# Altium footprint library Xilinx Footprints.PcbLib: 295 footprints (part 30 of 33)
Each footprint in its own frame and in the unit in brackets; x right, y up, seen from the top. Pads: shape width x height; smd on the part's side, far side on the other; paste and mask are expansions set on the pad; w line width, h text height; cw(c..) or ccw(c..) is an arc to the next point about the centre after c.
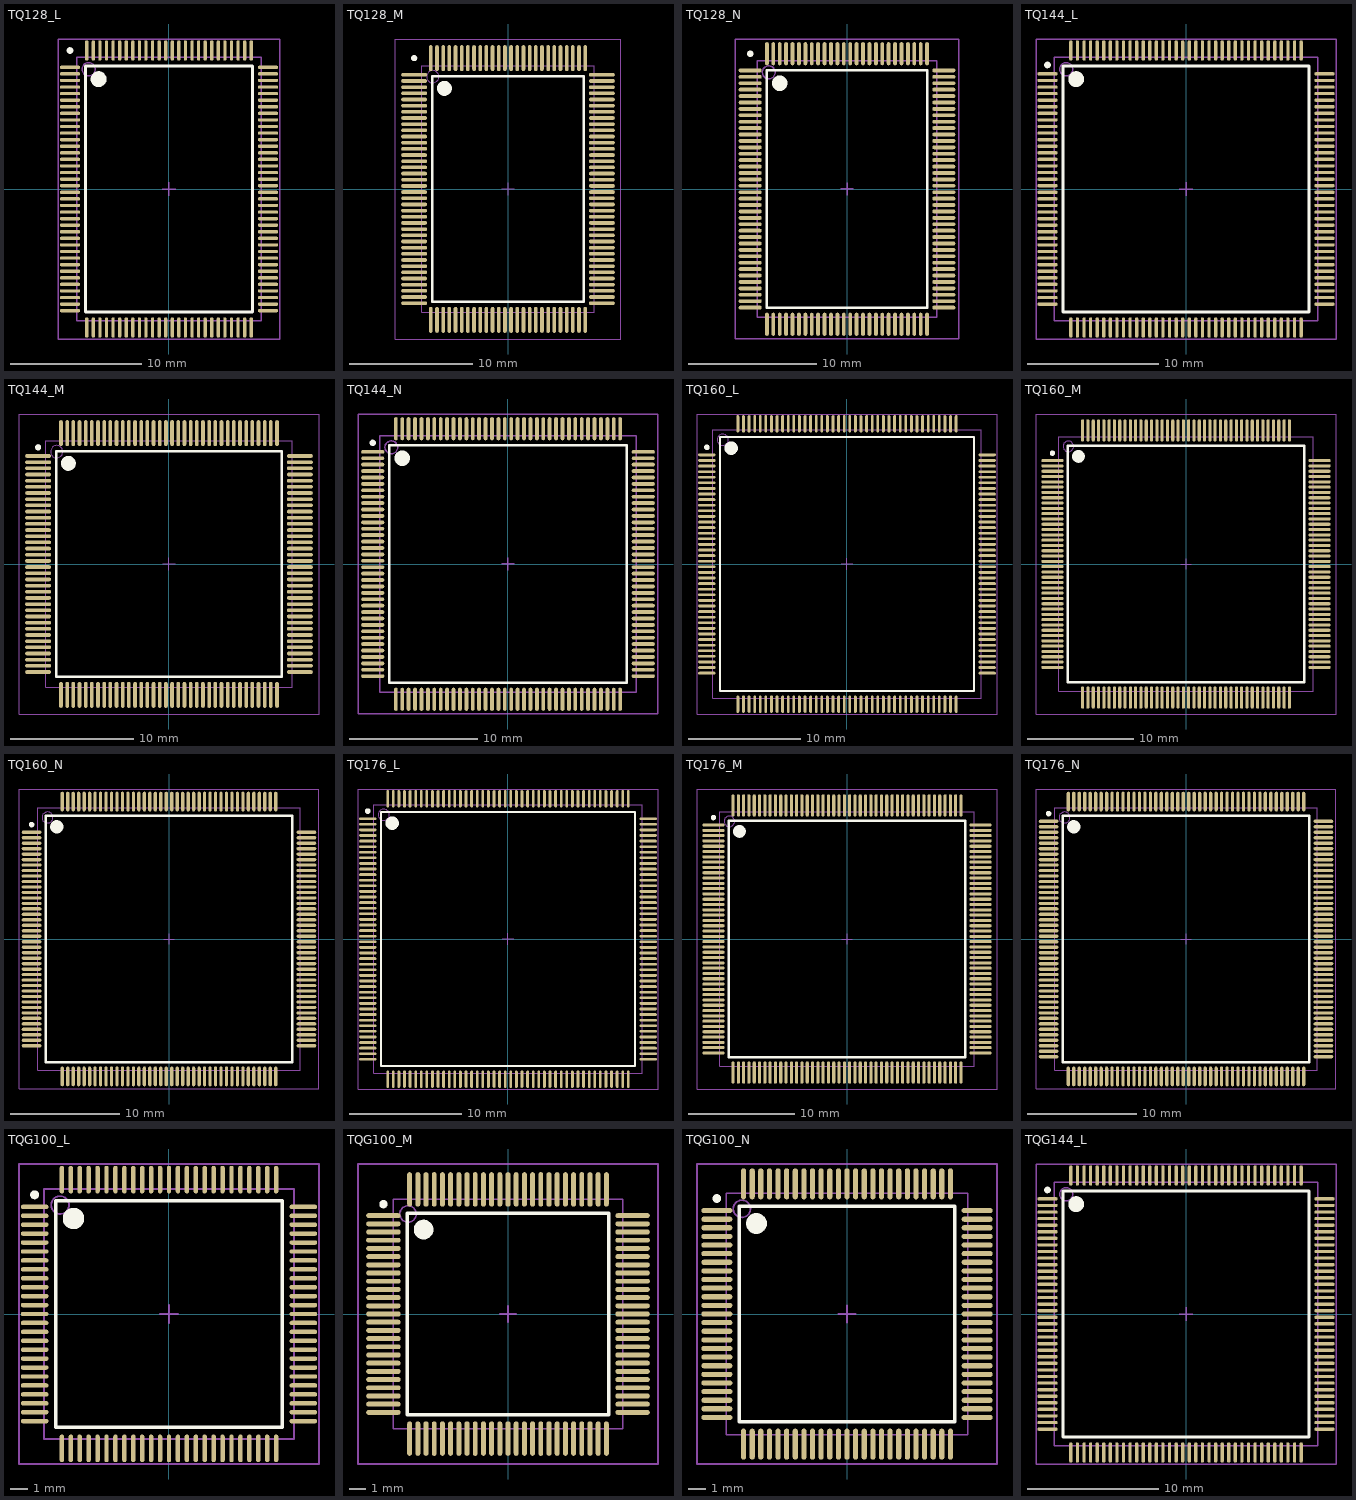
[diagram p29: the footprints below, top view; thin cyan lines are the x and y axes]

## TQ128_L [mm] "128-Pin Thin Quad Flat Pack (TQ128), IPC High Density"
height 1.6
pads (128):
  oval 1.55x0.25 smd: 1(-7.525,9.25) 2(-7.525,8.75) 3(-7.525,8.25) 4(-7.525,7.75) 5(-7.525,7.25) 6(-7.525,6.75) 7(-7.525,6.25) 8(-7.525,5.75) 9(-7.525,5.25) 10(-7.525,4.75) 11(-7.525,4.25) 12(-7.525,3.75) 13(-7.525,3.25) 14(-7.525,2.75) 15(-7.525,2.25) 16(-7.525,1.75) 17(-7.525,1.25) 18(-7.525,0.75) 19(-7.525,0.25) 20(-7.525,-0.25) 21(-7.525,-0.75) 22(-7.525,-1.25) 23(-7.525,-1.75) 24(-7.525,-2.25) 25(-7.525,-2.75) 26(-7.525,-3.25) 27(-7.525,-3.75) 28(-7.525,-4.25) 29(-7.525,-4.75) 30(-7.525,-5.25) 31(-7.525,-5.75) 32(-7.525,-6.25) 33(-7.525,-6.75) 34(-7.525,-7.25) 35(-7.525,-7.75) 36(-7.525,-8.25) 37(-7.525,-8.75) 38(-7.525,-9.25) 65(7.525,-9.25) 66(7.525,-8.75) 67(7.525,-8.25) 68(7.525,-7.75) 69(7.525,-7.25) 70(7.525,-6.75) 71(7.525,-6.25) 72(7.525,-5.75) 73(7.525,-5.25) 74(7.525,-4.75) 75(7.525,-4.25) 76(7.525,-3.75) 77(7.525,-3.25) 78(7.525,-2.75) 79(7.525,-2.25) 80(7.525,-1.75) 81(7.525,-1.25) 82(7.525,-0.75) 83(7.525,-0.25) 84(7.525,0.25) 85(7.525,0.75) 86(7.525,1.25) 87(7.525,1.75) 88(7.525,2.25) 89(7.525,2.75) 90(7.525,3.25) 91(7.525,3.75) 92(7.525,4.25) 93(7.525,4.75) 94(7.525,5.25) 95(7.525,5.75) 96(7.525,6.25) 97(7.525,6.75) 98(7.525,7.25) 99(7.525,7.75) 100(7.525,8.25) 101(7.525,8.75) 102(7.525,9.25)
  oval 0.25x1.55 smd: 39(-6.25,-10.525) 40(-5.75,-10.525) 41(-5.25,-10.525) 42(-4.75,-10.525) 43(-4.25,-10.525) 44(-3.75,-10.525) 45(-3.25,-10.525) 46(-2.75,-10.525) 47(-2.25,-10.525) 48(-1.75,-10.525) 49(-1.25,-10.525) 50(-0.75,-10.525) 51(-0.25,-10.525) 52(0.25,-10.525) 53(0.75,-10.525) 54(1.25,-10.525) 55(1.75,-10.525) 56(2.25,-10.525) 57(2.75,-10.525) 58(3.25,-10.525) 59(3.75,-10.525) 60(4.25,-10.525) 61(4.75,-10.525) 62(5.25,-10.525) 63(5.75,-10.525) 64(6.25,-10.525) 103(6.25,10.525) 104(5.75,10.525) 105(5.25,10.525) 106(4.75,10.525) 107(4.25,10.525) 108(3.75,10.525) 109(3.25,10.525) 110(2.75,10.525) 111(2.25,10.525) 112(1.75,10.525) 113(1.25,10.525) 114(0.75,10.525) 115(0.25,10.525) 116(-0.25,10.525) 117(-0.75,10.525) 118(-1.25,10.525) 119(-1.75,10.525) 120(-2.25,10.525) 121(-2.75,10.525) 122(-3.25,10.525) 123(-3.75,10.525) 124(-4.25,10.525) 125(-4.75,10.525) 126(-5.25,10.525) 127(-5.75,10.525) 128(-6.25,10.525)
Top Overlay:
  circle w0.6: c-5.35,8.35 r0.3
  circle w0.25: c-7.525,10.525 r0.125
  lines w0.2: -6.35,-9.35 6.35,-9.35 6.35,9.35 -6.35,9.35 -6.35,-9.35
Mechanical 13:
  circle w0.1: c-6.1,9.1 r0.5
  lines w0.1: -7,-10 7,-10 7,10 -7,10 -7,-10
Mechanical 15:
  lines w0.1: -0.5,0 0.5,0 ; 0,-0.5 0,0.5 ; -8.4,-11.4 8.4,-11.4 8.4,11.4 -8.4,11.4 -8.4,-11.4
3D body: height 1.6, standoff 0, extent -7,-10 7,10

## TQ128_M [mm] "128-Pin Thin Quad Flat Pack (TQ128), IPC Low Density"
height 1.6
pads (128):
  oval 2.1x0.3 smd: 1(-7.6,9.25) 2(-7.6,8.75) 3(-7.6,8.25) 4(-7.6,7.75) 5(-7.6,7.25) 6(-7.6,6.75) 7(-7.6,6.25) 8(-7.6,5.75) 9(-7.6,5.25) 10(-7.6,4.75) 11(-7.6,4.25) 12(-7.6,3.75) 13(-7.6,3.25) 14(-7.6,2.75) 15(-7.6,2.25) 16(-7.6,1.75) 17(-7.6,1.25) 18(-7.6,0.75) 19(-7.6,0.25) 20(-7.6,-0.25) 21(-7.6,-0.75) 22(-7.6,-1.25) 23(-7.6,-1.75) 24(-7.6,-2.25) 25(-7.6,-2.75) 26(-7.6,-3.25) 27(-7.6,-3.75) 28(-7.6,-4.25) 29(-7.6,-4.75) 30(-7.6,-5.25) 31(-7.6,-5.75) 32(-7.6,-6.25) 33(-7.6,-6.75) 34(-7.6,-7.25) 35(-7.6,-7.75) 36(-7.6,-8.25) 37(-7.6,-8.75) 38(-7.6,-9.25) 65(7.6,-9.25) 66(7.6,-8.75) 67(7.6,-8.25) 68(7.6,-7.75) 69(7.6,-7.25) 70(7.6,-6.75) 71(7.6,-6.25) 72(7.6,-5.75) 73(7.6,-5.25) 74(7.6,-4.75) 75(7.6,-4.25) 76(7.6,-3.75) 77(7.6,-3.25) 78(7.6,-2.75) 79(7.6,-2.25) 80(7.6,-1.75) 81(7.6,-1.25) 82(7.6,-0.75) 83(7.6,-0.25) 84(7.6,0.25) 85(7.6,0.75) 86(7.6,1.25) 87(7.6,1.75) 88(7.6,2.25) 89(7.6,2.75) 90(7.6,3.25) 91(7.6,3.75) 92(7.6,4.25) 93(7.6,4.75) 94(7.6,5.25) 95(7.6,5.75) 96(7.6,6.25) 97(7.6,6.75) 98(7.6,7.25) 99(7.6,7.75) 100(7.6,8.25) 101(7.6,8.75) 102(7.6,9.25)
  oval 0.3x2.1 smd: 39(-6.25,-10.6) 40(-5.75,-10.6) 41(-5.25,-10.6) 42(-4.75,-10.6) 43(-4.25,-10.6) 44(-3.75,-10.6) 45(-3.25,-10.6) 46(-2.75,-10.6) 47(-2.25,-10.6) 48(-1.75,-10.6) 49(-1.25,-10.6) 50(-0.75,-10.6) 51(-0.25,-10.6) 52(0.25,-10.6) 53(0.75,-10.6) 54(1.25,-10.6) 55(1.75,-10.6) 56(2.25,-10.6) 57(2.75,-10.6) 58(3.25,-10.6) 59(3.75,-10.6) 60(4.25,-10.6) 61(4.75,-10.6) 62(5.25,-10.6) 63(5.75,-10.6) 64(6.25,-10.6) 103(6.25,10.6) 104(5.75,10.6) 105(5.25,10.6) 106(4.75,10.6) 107(4.25,10.6) 108(3.75,10.6) 109(3.25,10.6) 110(2.75,10.6) 111(2.25,10.6) 112(1.75,10.6) 113(1.25,10.6) 114(0.75,10.6) 115(0.25,10.6) 116(-0.25,10.6) 117(-0.75,10.6) 118(-1.25,10.6) 119(-1.75,10.6) 120(-2.25,10.6) 121(-2.75,10.6) 122(-3.25,10.6) 123(-3.75,10.6) 124(-4.25,10.6) 125(-4.75,10.6) 126(-5.25,10.6) 127(-5.75,10.6) 128(-6.25,10.6)
Top Overlay:
  circle w0.25: c-7.6,10.6 r0.125
  circle w0.6: c-5.15,8.15 r0.3
  lines w0.2: -6.15,-9.15 -6.15,9.15 6.15,9.15 6.15,-9.15 -6.15,-9.15
Mechanical 13:
  circle w0.1: c-6.1,9.1 r0.5
  lines w0.1: -7,-10 -7,10 7,10 7,-10 -7,-10
Mechanical 15:
  lines w0.1: -0.5,0 0.5,0 ; 0,-0.5 0,0.5 ; -9.15,-12.15 -9.15,12.15 9.15,12.15 9.15,-12.15 -9.15,-12.15
3D body: height 1.6, standoff 0, extent -7,-10 7,10

## TQ128_N [mm] "128-Pin Thin Quad Flat Pack (TQ128), IPC Medium Density"
height 1.6
pads (128):
  oval 1.8x0.3 smd: 1(-7.55,9.25) 2(-7.55,8.75) 3(-7.55,8.25) 4(-7.55,7.75) 5(-7.55,7.25) 6(-7.55,6.75) 7(-7.55,6.25) 8(-7.55,5.75) 9(-7.55,5.25) 10(-7.55,4.75) 11(-7.55,4.25) 12(-7.55,3.75) 13(-7.55,3.25) 14(-7.55,2.75) 15(-7.55,2.25) 16(-7.55,1.75) 17(-7.55,1.25) 18(-7.55,0.75) 19(-7.55,0.25) 20(-7.55,-0.25) 21(-7.55,-0.75) 22(-7.55,-1.25) 23(-7.55,-1.75) 24(-7.55,-2.25) 25(-7.55,-2.75) 26(-7.55,-3.25) 27(-7.55,-3.75) 28(-7.55,-4.25) 29(-7.55,-4.75) 30(-7.55,-5.25) 31(-7.55,-5.75) 32(-7.55,-6.25) 33(-7.55,-6.75) 34(-7.55,-7.25) 35(-7.55,-7.75) 36(-7.55,-8.25) 37(-7.55,-8.75) 38(-7.55,-9.25) 65(7.55,-9.25) 66(7.55,-8.75) 67(7.55,-8.25) 68(7.55,-7.75) 69(7.55,-7.25) 70(7.55,-6.75) 71(7.55,-6.25) 72(7.55,-5.75) 73(7.55,-5.25) 74(7.55,-4.75) 75(7.55,-4.25) 76(7.55,-3.75) 77(7.55,-3.25) 78(7.55,-2.75) 79(7.55,-2.25) 80(7.55,-1.75) 81(7.55,-1.25) 82(7.55,-0.75) 83(7.55,-0.25) 84(7.55,0.25) 85(7.55,0.75) 86(7.55,1.25) 87(7.55,1.75) 88(7.55,2.25) 89(7.55,2.75) 90(7.55,3.25) 91(7.55,3.75) 92(7.55,4.25) 93(7.55,4.75) 94(7.55,5.25) 95(7.55,5.75) 96(7.55,6.25) 97(7.55,6.75) 98(7.55,7.25) 99(7.55,7.75) 100(7.55,8.25) 101(7.55,8.75) 102(7.55,9.25)
  oval 0.3x1.8 smd: 39(-6.25,-10.55) 40(-5.75,-10.55) 41(-5.25,-10.55) 42(-4.75,-10.55) 43(-4.25,-10.55) 44(-3.75,-10.55) 45(-3.25,-10.55) 46(-2.75,-10.55) 47(-2.25,-10.55) 48(-1.75,-10.55) 49(-1.25,-10.55) 50(-0.75,-10.55) 51(-0.25,-10.55) 52(0.25,-10.55) 53(0.75,-10.55) 54(1.25,-10.55) 55(1.75,-10.55) 56(2.25,-10.55) 57(2.75,-10.55) 58(3.25,-10.55) 59(3.75,-10.55) 60(4.25,-10.55) 61(4.75,-10.55) 62(5.25,-10.55) 63(5.75,-10.55) 64(6.25,-10.55) 103(6.25,10.55) 104(5.75,10.55) 105(5.25,10.55) 106(4.75,10.55) 107(4.25,10.55) 108(3.75,10.55) 109(3.25,10.55) 110(2.75,10.55) 111(2.25,10.55) 112(1.75,10.55) 113(1.25,10.55) 114(0.75,10.55) 115(0.25,10.55) 116(-0.25,10.55) 117(-0.75,10.55) 118(-1.25,10.55) 119(-1.75,10.55) 120(-2.25,10.55) 121(-2.75,10.55) 122(-3.25,10.55) 123(-3.75,10.55) 124(-4.25,10.55) 125(-4.75,10.55) 126(-5.25,10.55) 127(-5.75,10.55) 128(-6.25,10.55)
Top Overlay:
  circle w0.25: c-7.55,10.55 r0.125
  circle w0.6: c-5.25,8.25 r0.3
  lines w0.2: -6.25,-9.25 -6.25,9.25 6.25,9.25 6.25,-9.25 -6.25,-9.25
Mechanical 13:
  circle w0.1: c-6.1,9.1 r0.5
  lines w0.1: -7,-10 -7,10 7,10 7,-10 -7,-10
Mechanical 15:
  lines w0.1: -0.5,0 0.5,0 ; 0,-0.5 0,0.5 ; -8.7,-11.7 -8.7,11.7 8.7,11.7 8.7,-11.7 -8.7,-11.7
3D body: height 1.6, standoff 0, extent -7,-10 7,10

## TQ144_L [mm] "144-Pin Thin Quad Flat Pack (TQ144), IPC High Density"
height 1.6
pads (144):
  oval 1.55x0.25 smd: 1(-10.525,8.75) 2(-10.525,8.25) 3(-10.525,7.75) 4(-10.525,7.25) 5(-10.525,6.75) 6(-10.525,6.25) 7(-10.525,5.75) 8(-10.525,5.25) 9(-10.525,4.75) 10(-10.525,4.25) 11(-10.525,3.75) 12(-10.525,3.25) 13(-10.525,2.75) 14(-10.525,2.25) 15(-10.525,1.75) 16(-10.525,1.25) 17(-10.525,0.75) 18(-10.525,0.25) 19(-10.525,-0.25) 20(-10.525,-0.75) 21(-10.525,-1.25) 22(-10.525,-1.75) 23(-10.525,-2.25) 24(-10.525,-2.75) 25(-10.525,-3.25) 26(-10.525,-3.75) 27(-10.525,-4.25) 28(-10.525,-4.75) 29(-10.525,-5.25) 30(-10.525,-5.75) 31(-10.525,-6.25) 32(-10.525,-6.75) 33(-10.525,-7.25) 34(-10.525,-7.75) 35(-10.525,-8.25) 36(-10.525,-8.75) 73(10.525,-8.75) 74(10.525,-8.25) 75(10.525,-7.75) 76(10.525,-7.25) 77(10.525,-6.75) 78(10.525,-6.25) 79(10.525,-5.75) 80(10.525,-5.25) 81(10.525,-4.75) 82(10.525,-4.25) 83(10.525,-3.75) 84(10.525,-3.25) 85(10.525,-2.75) 86(10.525,-2.25) 87(10.525,-1.75) 88(10.525,-1.25) 89(10.525,-0.75) 90(10.525,-0.25) 91(10.525,0.25) 92(10.525,0.75) 93(10.525,1.25) 94(10.525,1.75) 95(10.525,2.25) 96(10.525,2.75) 97(10.525,3.25) 98(10.525,3.75) 99(10.525,4.25) 100(10.525,4.75) 101(10.525,5.25) 102(10.525,5.75) 103(10.525,6.25) 104(10.525,6.75) 105(10.525,7.25) 106(10.525,7.75) 107(10.525,8.25) 108(10.525,8.75)
  oval 0.25x1.55 smd: 37(-8.75,-10.525) 38(-8.25,-10.525) 39(-7.75,-10.525) 40(-7.25,-10.525) 41(-6.75,-10.525) 42(-6.25,-10.525) 43(-5.75,-10.525) 44(-5.25,-10.525) 45(-4.75,-10.525) 46(-4.25,-10.525) 47(-3.75,-10.525) 48(-3.25,-10.525) 49(-2.75,-10.525) 50(-2.25,-10.525) 51(-1.75,-10.525) 52(-1.25,-10.525) 53(-0.75,-10.525) 54(-0.25,-10.525) 55(0.25,-10.525) 56(0.75,-10.525) 57(1.25,-10.525) 58(1.75,-10.525) 59(2.25,-10.525) 60(2.75,-10.525) 61(3.25,-10.525) 62(3.75,-10.525) 63(4.25,-10.525) 64(4.75,-10.525) 65(5.25,-10.525) 66(5.75,-10.525) 67(6.25,-10.525) 68(6.75,-10.525) 69(7.25,-10.525) 70(7.75,-10.525) 71(8.25,-10.525) 72(8.75,-10.525) 109(8.75,10.525) 110(8.25,10.525) 111(7.75,10.525) 112(7.25,10.525) 113(6.75,10.525) 114(6.25,10.525) 115(5.75,10.525) 116(5.25,10.525) 117(4.75,10.525) 118(4.25,10.525) 119(3.75,10.525) 120(3.25,10.525) 121(2.75,10.525) 122(2.25,10.525) 123(1.75,10.525) 124(1.25,10.525) 125(0.75,10.525) 126(0.25,10.525) 127(-0.25,10.525) 128(-0.75,10.525) 129(-1.25,10.525) 130(-1.75,10.525) 131(-2.25,10.525) 132(-2.75,10.525) 133(-3.25,10.525) 134(-3.75,10.525) 135(-4.25,10.525) 136(-4.75,10.525) 137(-5.25,10.525) 138(-5.75,10.525) 139(-6.25,10.525) 140(-6.75,10.525) 141(-7.25,10.525) 142(-7.75,10.525) 143(-8.25,10.525) 144(-8.75,10.525)
Top Overlay:
  circle w0.6: c-8.35,8.35 r0.3
  circle w0.25: c-10.525,9.425 r0.125
  lines w0.2: -9.35,-9.35 9.35,-9.35 9.35,9.35 -9.35,9.35 -9.35,-9.35
Mechanical 13:
  circle w0.1: c-9.1,9.1 r0.5
  lines w0.1: -10,-10 10,-10 10,10 -10,10 -10,-10
Mechanical 15:
  lines w0.1: -0.5,0 0.5,0 ; 0,-0.5 0,0.5 ; -11.4,-11.4 11.4,-11.4 11.4,11.4 -11.4,11.4 -11.4,-11.4
3D body: height 1.6, standoff 0, extent -10,-10 10,10

## TQ144_M [mm] "144-Pin Thin Quad Flat Pack (TQ144), IPC Low Density"
height 1.6
pads (144):
  oval 2.1x0.3 smd: 1(-10.6,8.75) 2(-10.6,8.25) 3(-10.6,7.75) 4(-10.6,7.25) 5(-10.6,6.75) 6(-10.6,6.25) 7(-10.6,5.75) 8(-10.6,5.25) 9(-10.6,4.75) 10(-10.6,4.25) 11(-10.6,3.75) 12(-10.6,3.25) 13(-10.6,2.75) 14(-10.6,2.25) 15(-10.6,1.75) 16(-10.6,1.25) 17(-10.6,0.75) 18(-10.6,0.25) 19(-10.6,-0.25) 20(-10.6,-0.75) 21(-10.6,-1.25) 22(-10.6,-1.75) 23(-10.6,-2.25) 24(-10.6,-2.75) 25(-10.6,-3.25) 26(-10.6,-3.75) 27(-10.6,-4.25) 28(-10.6,-4.75) 29(-10.6,-5.25) 30(-10.6,-5.75) 31(-10.6,-6.25) 32(-10.6,-6.75) 33(-10.6,-7.25) 34(-10.6,-7.75) 35(-10.6,-8.25) 36(-10.6,-8.75) 73(10.6,-8.75) 74(10.6,-8.25) 75(10.6,-7.75) 76(10.6,-7.25) 77(10.6,-6.75) 78(10.6,-6.25) 79(10.6,-5.75) 80(10.6,-5.25) 81(10.6,-4.75) 82(10.6,-4.25) 83(10.6,-3.75) 84(10.6,-3.25) 85(10.6,-2.75) 86(10.6,-2.25) 87(10.6,-1.75) 88(10.6,-1.25) 89(10.6,-0.75) 90(10.6,-0.25) 91(10.6,0.25) 92(10.6,0.75) 93(10.6,1.25) 94(10.6,1.75) 95(10.6,2.25) 96(10.6,2.75) 97(10.6,3.25) 98(10.6,3.75) 99(10.6,4.25) 100(10.6,4.75) 101(10.6,5.25) 102(10.6,5.75) 103(10.6,6.25) 104(10.6,6.75) 105(10.6,7.25) 106(10.6,7.75) 107(10.6,8.25) 108(10.6,8.75)
  oval 0.3x2.1 smd: 37(-8.75,-10.6) 38(-8.25,-10.6) 39(-7.75,-10.6) 40(-7.25,-10.6) 41(-6.75,-10.6) 42(-6.25,-10.6) 43(-5.75,-10.6) 44(-5.25,-10.6) 45(-4.75,-10.6) 46(-4.25,-10.6) 47(-3.75,-10.6) 48(-3.25,-10.6) 49(-2.75,-10.6) 50(-2.25,-10.6) 51(-1.75,-10.6) 52(-1.25,-10.6) 53(-0.75,-10.6) 54(-0.25,-10.6) 55(0.25,-10.6) 56(0.75,-10.6) 57(1.25,-10.6) 58(1.75,-10.6) 59(2.25,-10.6) 60(2.75,-10.6) 61(3.25,-10.6) 62(3.75,-10.6) 63(4.25,-10.6) 64(4.75,-10.6) 65(5.25,-10.6) 66(5.75,-10.6) 67(6.25,-10.6) 68(6.75,-10.6) 69(7.25,-10.6) 70(7.75,-10.6) 71(8.25,-10.6) 72(8.75,-10.6) 109(8.75,10.6) 110(8.25,10.6) 111(7.75,10.6) 112(7.25,10.6) 113(6.75,10.6) 114(6.25,10.6) 115(5.75,10.6) 116(5.25,10.6) 117(4.75,10.6) 118(4.25,10.6) 119(3.75,10.6) 120(3.25,10.6) 121(2.75,10.6) 122(2.25,10.6) 123(1.75,10.6) 124(1.25,10.6) 125(0.75,10.6) 126(0.25,10.6) 127(-0.25,10.6) 128(-0.75,10.6) 129(-1.25,10.6) 130(-1.75,10.6) 131(-2.25,10.6) 132(-2.75,10.6) 133(-3.25,10.6) 134(-3.75,10.6) 135(-4.25,10.6) 136(-4.75,10.6) 137(-5.25,10.6) 138(-5.75,10.6) 139(-6.25,10.6) 140(-6.75,10.6) 141(-7.25,10.6) 142(-7.75,10.6) 143(-8.25,10.6) 144(-8.75,10.6)
Top Overlay:
  circle w0.6: c-8.15,8.15 r0.3
  circle w0.25: c-10.6,9.45 r0.125
  lines w0.2: -9.15,-9.15 9.15,-9.15 9.15,9.15 -9.15,9.15 -9.15,-9.15
Mechanical 13:
  circle w0.1: c-9.1,9.1 r0.5
  lines w0.1: -10,-10 10,-10 10,10 -10,10 -10,-10
Mechanical 15:
  lines w0.1: -0.5,0 0.5,0 ; 0,-0.5 0,0.5 ; -12.15,-12.15 12.15,-12.15 12.15,12.15 -12.15,12.15 -12.15,-12.15
3D body: height 1.6, standoff 0, extent -10,-10 10,10

## TQ144_N [mm] "144-Pin Thin Quad Flat Pack (TQ144), IPC Medium Density"
height 1.6
pads (144):
  oval 1.8x0.3 smd: 1(-10.55,8.75) 2(-10.55,8.25) 3(-10.55,7.75) 4(-10.55,7.25) 5(-10.55,6.75) 6(-10.55,6.25) 7(-10.55,5.75) 8(-10.55,5.25) 9(-10.55,4.75) 10(-10.55,4.25) 11(-10.55,3.75) 12(-10.55,3.25) 13(-10.55,2.75) 14(-10.55,2.25) 15(-10.55,1.75) 16(-10.55,1.25) 17(-10.55,0.75) 18(-10.55,0.25) 19(-10.55,-0.25) 20(-10.55,-0.75) 21(-10.55,-1.25) 22(-10.55,-1.75) 23(-10.55,-2.25) 24(-10.55,-2.75) 25(-10.55,-3.25) 26(-10.55,-3.75) 27(-10.55,-4.25) 28(-10.55,-4.75) 29(-10.55,-5.25) 30(-10.55,-5.75) 31(-10.55,-6.25) 32(-10.55,-6.75) 33(-10.55,-7.25) 34(-10.55,-7.75) 35(-10.55,-8.25) 36(-10.55,-8.75) 73(10.55,-8.75) 74(10.55,-8.25) 75(10.55,-7.75) 76(10.55,-7.25) 77(10.55,-6.75) 78(10.55,-6.25) 79(10.55,-5.75) 80(10.55,-5.25) 81(10.55,-4.75) 82(10.55,-4.25) 83(10.55,-3.75) 84(10.55,-3.25) 85(10.55,-2.75) 86(10.55,-2.25) 87(10.55,-1.75) 88(10.55,-1.25) 89(10.55,-0.75) 90(10.55,-0.25) 91(10.55,0.25) 92(10.55,0.75) 93(10.55,1.25) 94(10.55,1.75) 95(10.55,2.25) 96(10.55,2.75) 97(10.55,3.25) 98(10.55,3.75) 99(10.55,4.25) 100(10.55,4.75) 101(10.55,5.25) 102(10.55,5.75) 103(10.55,6.25) 104(10.55,6.75) 105(10.55,7.25) 106(10.55,7.75) 107(10.55,8.25) 108(10.55,8.75)
  oval 0.3x1.8 smd: 37(-8.75,-10.55) 38(-8.25,-10.55) 39(-7.75,-10.55) 40(-7.25,-10.55) 41(-6.75,-10.55) 42(-6.25,-10.55) 43(-5.75,-10.55) 44(-5.25,-10.55) 45(-4.75,-10.55) 46(-4.25,-10.55) 47(-3.75,-10.55) 48(-3.25,-10.55) 49(-2.75,-10.55) 50(-2.25,-10.55) 51(-1.75,-10.55) 52(-1.25,-10.55) 53(-0.75,-10.55) 54(-0.25,-10.55) 55(0.25,-10.55) 56(0.75,-10.55) 57(1.25,-10.55) 58(1.75,-10.55) 59(2.25,-10.55) 60(2.75,-10.55) 61(3.25,-10.55) 62(3.75,-10.55) 63(4.25,-10.55) 64(4.75,-10.55) 65(5.25,-10.55) 66(5.75,-10.55) 67(6.25,-10.55) 68(6.75,-10.55) 69(7.25,-10.55) 70(7.75,-10.55) 71(8.25,-10.55) 72(8.75,-10.55) 109(8.75,10.55) 110(8.25,10.55) 111(7.75,10.55) 112(7.25,10.55) 113(6.75,10.55) 114(6.25,10.55) 115(5.75,10.55) 116(5.25,10.55) 117(4.75,10.55) 118(4.25,10.55) 119(3.75,10.55) 120(3.25,10.55) 121(2.75,10.55) 122(2.25,10.55) 123(1.75,10.55) 124(1.25,10.55) 125(0.75,10.55) 126(0.25,10.55) 127(-0.25,10.55) 128(-0.75,10.55) 129(-1.25,10.55) 130(-1.75,10.55) 131(-2.25,10.55) 132(-2.75,10.55) 133(-3.25,10.55) 134(-3.75,10.55) 135(-4.25,10.55) 136(-4.75,10.55) 137(-5.25,10.55) 138(-5.75,10.55) 139(-6.25,10.55) 140(-6.75,10.55) 141(-7.25,10.55) 142(-7.75,10.55) 143(-8.25,10.55) 144(-8.75,10.55)
Top Overlay:
  circle w0.25: c-10.55,9.45 r0.125
  circle w0.6: c-8.25,8.25 r0.3
  lines w0.2: -9.25,-9.25 -9.25,9.25 9.25,9.25 9.25,-9.25 -9.25,-9.25
Mechanical 13:
  circle w0.1: c-9.1,9.1 r0.5
  lines w0.1: -10,-10 -10,10 10,10 10,-10 -10,-10
Mechanical 15:
  lines w0.1: -0.5,0 0.5,0 ; 0,-0.5 0,0.5 ; -11.7,-11.7 -11.7,11.7 11.7,11.7 11.7,-11.7 -11.7,-11.7
3D body: height 1.6, standoff 0, extent -10,-10 10,10

## TQ160_L [mm] "160-Pin Thin Quad Flat Pack (TQ160), IPC High Density"
height 1.6
pads (160):
  oval 1.55x0.25 smd: 1(-12.525,9.75) 2(-12.525,9.25) 3(-12.525,8.75) 4(-12.525,8.25) 5(-12.525,7.75) 6(-12.525,7.25) 7(-12.525,6.75) 8(-12.525,6.25) 9(-12.525,5.75) 10(-12.525,5.25) 11(-12.525,4.75) 12(-12.525,4.25) 13(-12.525,3.75) 14(-12.525,3.25) 15(-12.525,2.75) 16(-12.525,2.25) 17(-12.525,1.75) 18(-12.525,1.25) 19(-12.525,0.75) 20(-12.525,0.25) 21(-12.525,-0.25) 22(-12.525,-0.75) 23(-12.525,-1.25) 24(-12.525,-1.75) 25(-12.525,-2.25) 26(-12.525,-2.75) 27(-12.525,-3.25) 28(-12.525,-3.75) 29(-12.525,-4.25) 30(-12.525,-4.75) 31(-12.525,-5.25) 32(-12.525,-5.75) 33(-12.525,-6.25) 34(-12.525,-6.75) 35(-12.525,-7.25) 36(-12.525,-7.75) 37(-12.525,-8.25) 38(-12.525,-8.75) 39(-12.525,-9.25) 40(-12.525,-9.75) 81(12.525,-9.75) 82(12.525,-9.25) 83(12.525,-8.75) 84(12.525,-8.25) 85(12.525,-7.75) 86(12.525,-7.25) 87(12.525,-6.75) 88(12.525,-6.25) 89(12.525,-5.75) 90(12.525,-5.25) 91(12.525,-4.75) 92(12.525,-4.25) 93(12.525,-3.75) 94(12.525,-3.25) 95(12.525,-2.75) 96(12.525,-2.25) 97(12.525,-1.75) 98(12.525,-1.25) 99(12.525,-0.75) 100(12.525,-0.25) 101(12.525,0.25) 102(12.525,0.75) 103(12.525,1.25) 104(12.525,1.75) 105(12.525,2.25) 106(12.525,2.75) 107(12.525,3.25) 108(12.525,3.75) 109(12.525,4.25) 110(12.525,4.75) 111(12.525,5.25) 112(12.525,5.75) 113(12.525,6.25) 114(12.525,6.75) 115(12.525,7.25) 116(12.525,7.75) 117(12.525,8.25) 118(12.525,8.75) 119(12.525,9.25) 120(12.525,9.75)
  oval 0.25x1.55 smd: 41(-9.75,-12.525) 42(-9.25,-12.525) 43(-8.75,-12.525) 44(-8.25,-12.525) 45(-7.75,-12.525) 46(-7.25,-12.525) 47(-6.75,-12.525) 48(-6.25,-12.525) 49(-5.75,-12.525) 50(-5.25,-12.525) 51(-4.75,-12.525) 52(-4.25,-12.525) 53(-3.75,-12.525) 54(-3.25,-12.525) 55(-2.75,-12.525) 56(-2.25,-12.525) 57(-1.75,-12.525) 58(-1.25,-12.525) 59(-0.75,-12.525) 60(-0.25,-12.525) 61(0.25,-12.525) 62(0.75,-12.525) 63(1.25,-12.525) 64(1.75,-12.525) 65(2.25,-12.525) 66(2.75,-12.525) 67(3.25,-12.525) 68(3.75,-12.525) 69(4.25,-12.525) 70(4.75,-12.525) 71(5.25,-12.525) 72(5.75,-12.525) 73(6.25,-12.525) 74(6.75,-12.525) 75(7.25,-12.525) 76(7.75,-12.525) 77(8.25,-12.525) 78(8.75,-12.525) 79(9.25,-12.525) 80(9.75,-12.525) 121(9.75,12.525) 122(9.25,12.525) 123(8.75,12.525) 124(8.25,12.525) 125(7.75,12.525) 126(7.25,12.525) 127(6.75,12.525) 128(6.25,12.525) 129(5.75,12.525) 130(5.25,12.525) 131(4.75,12.525) 132(4.25,12.525) 133(3.75,12.525) 134(3.25,12.525) 135(2.75,12.525) 136(2.25,12.525) 137(1.75,12.525) 138(1.25,12.525) 139(0.75,12.525) 140(0.25,12.525) 141(-0.25,12.525) 142(-0.75,12.525) 143(-1.25,12.525) 144(-1.75,12.525) 145(-2.25,12.525) 146(-2.75,12.525) 147(-3.25,12.525) 148(-3.75,12.525) 149(-4.25,12.525) 150(-4.75,12.525) 151(-5.25,12.525) 152(-5.75,12.525) 153(-6.25,12.525) 154(-6.75,12.525) 155(-7.25,12.525) 156(-7.75,12.525) 157(-8.25,12.525) 158(-8.75,12.525) 159(-9.25,12.525) 160(-9.75,12.525)
Top Overlay:
  circle w0.6: c-10.35,10.35 r0.3
  circle w0.25: c-12.525,10.425 r0.125
  lines w0.2: -11.35,-11.35 11.35,-11.35 11.35,11.35 -11.35,11.35 -11.35,-11.35
Mechanical 13:
  circle w0.1: c-11.1,11.1 r0.5
  lines w0.1: -12,-12 12,-12 12,12 -12,12 -12,-12
Mechanical 15:
  lines w0.1: -0.5,0 0.5,0 ; 0,-0.5 0,0.5 ; -13.4,-13.4 13.4,-13.4 13.4,13.4 -13.4,13.4 -13.4,-13.4
3D body: height 1.6, standoff 0, extent -12,-12 12,12

## TQ160_M [mm] "160-Pin Thin Quad Flat Pack (TQ160), IPC Low Density"
height 1.6
pads (160):
  oval 2.1x0.3 smd: 1(-12.6,9.75) 2(-12.6,9.25) 3(-12.6,8.75) 4(-12.6,8.25) 5(-12.6,7.75) 6(-12.6,7.25) 7(-12.6,6.75) 8(-12.6,6.25) 9(-12.6,5.75) 10(-12.6,5.25) 11(-12.6,4.75) 12(-12.6,4.25) 13(-12.6,3.75) 14(-12.6,3.25) 15(-12.6,2.75) 16(-12.6,2.25) 17(-12.6,1.75) 18(-12.6,1.25) 19(-12.6,0.75) 20(-12.6,0.25) 21(-12.6,-0.25) 22(-12.6,-0.75) 23(-12.6,-1.25) 24(-12.6,-1.75) 25(-12.6,-2.25) 26(-12.6,-2.75) 27(-12.6,-3.25) 28(-12.6,-3.75) 29(-12.6,-4.25) 30(-12.6,-4.75) 31(-12.6,-5.25) 32(-12.6,-5.75) 33(-12.6,-6.25) 34(-12.6,-6.75) 35(-12.6,-7.25) 36(-12.6,-7.75) 37(-12.6,-8.25) 38(-12.6,-8.75) 39(-12.6,-9.25) 40(-12.6,-9.75) 81(12.6,-9.75) 82(12.6,-9.25) 83(12.6,-8.75) 84(12.6,-8.25) 85(12.6,-7.75) 86(12.6,-7.25) 87(12.6,-6.75) 88(12.6,-6.25) 89(12.6,-5.75) 90(12.6,-5.25) 91(12.6,-4.75) 92(12.6,-4.25) 93(12.6,-3.75) 94(12.6,-3.25) 95(12.6,-2.75) 96(12.6,-2.25) 97(12.6,-1.75) 98(12.6,-1.25) 99(12.6,-0.75) 100(12.6,-0.25) 101(12.6,0.25) 102(12.6,0.75) 103(12.6,1.25) 104(12.6,1.75) 105(12.6,2.25) 106(12.6,2.75) 107(12.6,3.25) 108(12.6,3.75) 109(12.6,4.25) 110(12.6,4.75) 111(12.6,5.25) 112(12.6,5.75) 113(12.6,6.25) 114(12.6,6.75) 115(12.6,7.25) 116(12.6,7.75) 117(12.6,8.25) 118(12.6,8.75) 119(12.6,9.25) 120(12.6,9.75)
  oval 0.3x2.1 smd: 41(-9.75,-12.6) 42(-9.25,-12.6) 43(-8.75,-12.6) 44(-8.25,-12.6) 45(-7.75,-12.6) 46(-7.25,-12.6) 47(-6.75,-12.6) 48(-6.25,-12.6) 49(-5.75,-12.6) 50(-5.25,-12.6) 51(-4.75,-12.6) 52(-4.25,-12.6) 53(-3.75,-12.6) 54(-3.25,-12.6) 55(-2.75,-12.6) 56(-2.25,-12.6) 57(-1.75,-12.6) 58(-1.25,-12.6) 59(-0.75,-12.6) 60(-0.25,-12.6) 61(0.25,-12.6) 62(0.75,-12.6) 63(1.25,-12.6) 64(1.75,-12.6) 65(2.25,-12.6) 66(2.75,-12.6) 67(3.25,-12.6) 68(3.75,-12.6) 69(4.25,-12.6) 70(4.75,-12.6) 71(5.25,-12.6) 72(5.75,-12.6) 73(6.25,-12.6) 74(6.75,-12.6) 75(7.25,-12.6) 76(7.75,-12.6) 77(8.25,-12.6) 78(8.75,-12.6) 79(9.25,-12.6) 80(9.75,-12.6) 121(9.75,12.6) 122(9.25,12.6) 123(8.75,12.6) 124(8.25,12.6) 125(7.75,12.6) 126(7.25,12.6) 127(6.75,12.6) 128(6.25,12.6) 129(5.75,12.6) 130(5.25,12.6) 131(4.75,12.6) 132(4.25,12.6) 133(3.75,12.6) 134(3.25,12.6) 135(2.75,12.6) 136(2.25,12.6) 137(1.75,12.6) 138(1.25,12.6) 139(0.75,12.6) 140(0.25,12.6) 141(-0.25,12.6) 142(-0.75,12.6) 143(-1.25,12.6) 144(-1.75,12.6) 145(-2.25,12.6) 146(-2.75,12.6) 147(-3.25,12.6) 148(-3.75,12.6) 149(-4.25,12.6) 150(-4.75,12.6) 151(-5.25,12.6) 152(-5.75,12.6) 153(-6.25,12.6) 154(-6.75,12.6) 155(-7.25,12.6) 156(-7.75,12.6) 157(-8.25,12.6) 158(-8.75,12.6) 159(-9.25,12.6) 160(-9.75,12.6)
Top Overlay:
  circle w0.6: c-10.15,10.15 r0.3
  circle w0.25: c-12.6,10.45 r0.125
  lines w0.2: -11.15,-11.15 11.15,-11.15 11.15,11.15 -11.15,11.15 -11.15,-11.15
Mechanical 13:
  circle w0.1: c-11.1,11.1 r0.5
  lines w0.1: -12,-12 12,-12 12,12 -12,12 -12,-12
Mechanical 15:
  lines w0.1: -0.5,0 0.5,0 ; 0,-0.5 0,0.5 ; -14.15,-14.15 14.15,-14.15 14.15,14.15 -14.15,14.15 -14.15,-14.15
3D body: height 1.6, standoff 0, extent -12,-12 12,12

## TQ160_N [mm] "160-Pin Thin Quad Flat Pack (TQ160), IPC Medium Density"
height 1.6
pads (160):
  oval 1.8x0.3 smd: 1(-12.55,9.75) 2(-12.55,9.25) 3(-12.55,8.75) 4(-12.55,8.25) 5(-12.55,7.75) 6(-12.55,7.25) 7(-12.55,6.75) 8(-12.55,6.25) 9(-12.55,5.75) 10(-12.55,5.25) 11(-12.55,4.75) 12(-12.55,4.25) 13(-12.55,3.75) 14(-12.55,3.25) 15(-12.55,2.75) 16(-12.55,2.25) 17(-12.55,1.75) 18(-12.55,1.25) 19(-12.55,0.75) 20(-12.55,0.25) 21(-12.55,-0.25) 22(-12.55,-0.75) 23(-12.55,-1.25) 24(-12.55,-1.75) 25(-12.55,-2.25) 26(-12.55,-2.75) 27(-12.55,-3.25) 28(-12.55,-3.75) 29(-12.55,-4.25) 30(-12.55,-4.75) 31(-12.55,-5.25) 32(-12.55,-5.75) 33(-12.55,-6.25) 34(-12.55,-6.75) 35(-12.55,-7.25) 36(-12.55,-7.75) 37(-12.55,-8.25) 38(-12.55,-8.75) 39(-12.55,-9.25) 40(-12.55,-9.75) 81(12.55,-9.75) 82(12.55,-9.25) 83(12.55,-8.75) 84(12.55,-8.25) 85(12.55,-7.75) 86(12.55,-7.25) 87(12.55,-6.75) 88(12.55,-6.25) 89(12.55,-5.75) 90(12.55,-5.25) 91(12.55,-4.75) 92(12.55,-4.25) 93(12.55,-3.75) 94(12.55,-3.25) 95(12.55,-2.75) 96(12.55,-2.25) 97(12.55,-1.75) 98(12.55,-1.25) 99(12.55,-0.75) 100(12.55,-0.25) 101(12.55,0.25) 102(12.55,0.75) 103(12.55,1.25) 104(12.55,1.75) 105(12.55,2.25) 106(12.55,2.75) 107(12.55,3.25) 108(12.55,3.75) 109(12.55,4.25) 110(12.55,4.75) 111(12.55,5.25) 112(12.55,5.75) 113(12.55,6.25) 114(12.55,6.75) 115(12.55,7.25) 116(12.55,7.75) 117(12.55,8.25) 118(12.55,8.75) 119(12.55,9.25) 120(12.55,9.75)
  oval 0.3x1.8 smd: 41(-9.75,-12.55) 42(-9.25,-12.55) 43(-8.75,-12.55) 44(-8.25,-12.55) 45(-7.75,-12.55) 46(-7.25,-12.55) 47(-6.75,-12.55) 48(-6.25,-12.55) 49(-5.75,-12.55) 50(-5.25,-12.55) 51(-4.75,-12.55) 52(-4.25,-12.55) 53(-3.75,-12.55) 54(-3.25,-12.55) 55(-2.75,-12.55) 56(-2.25,-12.55) 57(-1.75,-12.55) 58(-1.25,-12.55) 59(-0.75,-12.55) 60(-0.25,-12.55) 61(0.25,-12.55) 62(0.75,-12.55) 63(1.25,-12.55) 64(1.75,-12.55) 65(2.25,-12.55) 66(2.75,-12.55) 67(3.25,-12.55) 68(3.75,-12.55) 69(4.25,-12.55) 70(4.75,-12.55) 71(5.25,-12.55) 72(5.75,-12.55) 73(6.25,-12.55) 74(6.75,-12.55) 75(7.25,-12.55) 76(7.75,-12.55) 77(8.25,-12.55) 78(8.75,-12.55) 79(9.25,-12.55) 80(9.75,-12.55) 121(9.75,12.55) 122(9.25,12.55) 123(8.75,12.55) 124(8.25,12.55) 125(7.75,12.55) 126(7.25,12.55) 127(6.75,12.55) 128(6.25,12.55) 129(5.75,12.55) 130(5.25,12.55) 131(4.75,12.55) 132(4.25,12.55) 133(3.75,12.55) 134(3.25,12.55) 135(2.75,12.55) 136(2.25,12.55) 137(1.75,12.55) 138(1.25,12.55) 139(0.75,12.55) 140(0.25,12.55) 141(-0.25,12.55) 142(-0.75,12.55) 143(-1.25,12.55) 144(-1.75,12.55) 145(-2.25,12.55) 146(-2.75,12.55) 147(-3.25,12.55) 148(-3.75,12.55) 149(-4.25,12.55) 150(-4.75,12.55) 151(-5.25,12.55) 152(-5.75,12.55) 153(-6.25,12.55) 154(-6.75,12.55) 155(-7.25,12.55) 156(-7.75,12.55) 157(-8.25,12.55) 158(-8.75,12.55) 159(-9.25,12.55) 160(-9.75,12.55)
Top Overlay:
  circle w0.6: c-10.25,10.25 r0.3
  circle w0.25: c-12.55,10.45 r0.125
  lines w0.2: -11.25,-11.25 11.25,-11.25 11.25,11.25 -11.25,11.25 -11.25,-11.25
Mechanical 13:
  circle w0.1: c-11.1,11.1 r0.5
  lines w0.1: -12,-12 12,-12 12,12 -12,12 -12,-12
Mechanical 15:
  lines w0.1: -0.5,0 0.5,0 ; 0,-0.5 0,0.5 ; -13.7,-13.7 13.7,-13.7 13.7,13.7 -13.7,13.7 -13.7,-13.7
3D body: height 1.6, standoff 0, extent -12,-12 12,12

## TQ176_L [mm] "176-Pin Thin Quad Flat Pack (TQ176), IPC High Density"
height 1.6
pads (176):
  oval 1.55x0.25 smd: 1(-12.525,10.75) 2(-12.525,10.25) 3(-12.525,9.75) 4(-12.525,9.25) 5(-12.525,8.75) 6(-12.525,8.25) 7(-12.525,7.75) 8(-12.525,7.25) 9(-12.525,6.75) 10(-12.525,6.25) 11(-12.525,5.75) 12(-12.525,5.25) 13(-12.525,4.75) 14(-12.525,4.25) 15(-12.525,3.75) 16(-12.525,3.25) 17(-12.525,2.75) 18(-12.525,2.25) 19(-12.525,1.75) 20(-12.525,1.25) 21(-12.525,0.75) 22(-12.525,0.25) 23(-12.525,-0.25) 24(-12.525,-0.75) 25(-12.525,-1.25) 26(-12.525,-1.75) 27(-12.525,-2.25) 28(-12.525,-2.75) 29(-12.525,-3.25) 30(-12.525,-3.75) 31(-12.525,-4.25) 32(-12.525,-4.75) 33(-12.525,-5.25) 34(-12.525,-5.75) 35(-12.525,-6.25) 36(-12.525,-6.75) 37(-12.525,-7.25) 38(-12.525,-7.75) 39(-12.525,-8.25) 40(-12.525,-8.75) 41(-12.525,-9.25) 42(-12.525,-9.75) 43(-12.525,-10.25) 44(-12.525,-10.75) 89(12.525,-10.75) 90(12.525,-10.25) 91(12.525,-9.75) 92(12.525,-9.25) 93(12.525,-8.75) 94(12.525,-8.25) 95(12.525,-7.75) 96(12.525,-7.25) 97(12.525,-6.75) 98(12.525,-6.25) 99(12.525,-5.75) 100(12.525,-5.25) 101(12.525,-4.75) 102(12.525,-4.25) 103(12.525,-3.75) 104(12.525,-3.25) 105(12.525,-2.75) 106(12.525,-2.25) 107(12.525,-1.75) 108(12.525,-1.25) 109(12.525,-0.75) 110(12.525,-0.25) 111(12.525,0.25) 112(12.525,0.75) 113(12.525,1.25) 114(12.525,1.75) 115(12.525,2.25) 116(12.525,2.75) 117(12.525,3.25) 118(12.525,3.75) 119(12.525,4.25) 120(12.525,4.75) 121(12.525,5.25) 122(12.525,5.75) 123(12.525,6.25) 124(12.525,6.75) 125(12.525,7.25) 126(12.525,7.75) 127(12.525,8.25) 128(12.525,8.75) 129(12.525,9.25) 130(12.525,9.75) 131(12.525,10.25) 132(12.525,10.75)
  oval 0.25x1.55 smd: 45(-10.75,-12.525) 46(-10.25,-12.525) 47(-9.75,-12.525) 48(-9.25,-12.525) 49(-8.75,-12.525) 50(-8.25,-12.525) 51(-7.75,-12.525) 52(-7.25,-12.525) 53(-6.75,-12.525) 54(-6.25,-12.525) 55(-5.75,-12.525) 56(-5.25,-12.525) 57(-4.75,-12.525) 58(-4.25,-12.525) 59(-3.75,-12.525) 60(-3.25,-12.525) 61(-2.75,-12.525) 62(-2.25,-12.525) 63(-1.75,-12.525) 64(-1.25,-12.525) 65(-0.75,-12.525) 66(-0.25,-12.525) 67(0.25,-12.525) 68(0.75,-12.525) 69(1.25,-12.525) 70(1.75,-12.525) 71(2.25,-12.525) 72(2.75,-12.525) 73(3.25,-12.525) 74(3.75,-12.525) 75(4.25,-12.525) 76(4.75,-12.525) 77(5.25,-12.525) 78(5.75,-12.525) 79(6.25,-12.525) 80(6.75,-12.525) 81(7.25,-12.525) 82(7.75,-12.525) 83(8.25,-12.525) 84(8.75,-12.525) 85(9.25,-12.525) 86(9.75,-12.525) 87(10.25,-12.525) 88(10.75,-12.525) 133(10.75,12.525) 134(10.25,12.525) 135(9.75,12.525) 136(9.25,12.525) 137(8.75,12.525) 138(8.25,12.525) 139(7.75,12.525) 140(7.25,12.525) 141(6.75,12.525) 142(6.25,12.525) 143(5.75,12.525) 144(5.25,12.525) 145(4.75,12.525) 146(4.25,12.525) 147(3.75,12.525) 148(3.25,12.525) 149(2.75,12.525) 150(2.25,12.525) 151(1.75,12.525) 152(1.25,12.525) 153(0.75,12.525) 154(0.25,12.525) 155(-0.25,12.525) 156(-0.75,12.525) 157(-1.25,12.525) 158(-1.75,12.525) 159(-2.25,12.525) 160(-2.75,12.525) 161(-3.25,12.525) 162(-3.75,12.525) 163(-4.25,12.525) 164(-4.75,12.525) 165(-5.25,12.525) 166(-5.75,12.525) 167(-6.25,12.525) 168(-6.75,12.525) 169(-7.25,12.525) 170(-7.75,12.525) 171(-8.25,12.525) 172(-8.75,12.525) 173(-9.25,12.525) 174(-9.75,12.525) 175(-10.25,12.525) 176(-10.75,12.525)
Top Overlay:
  circle w0.6: c-10.35,10.35 r0.3
  circle w0.25: c-12.525,11.425 r0.125
  lines w0.2: -11.35,-11.35 11.35,-11.35 11.35,11.35 -11.35,11.35 -11.35,-11.35
Mechanical 13:
  circle w0.1: c-11.1,11.1 r0.5
  lines w0.1: -12,-12 12,-12 12,12 -12,12 -12,-12
Mechanical 15:
  lines w0.1: -0.5,0 0.5,0 ; 0,-0.5 0,0.5 ; -13.4,-13.4 13.4,-13.4 13.4,13.4 -13.4,13.4 -13.4,-13.4
3D body: height 1.6, standoff 0, extent -12,-12 12,12

## TQ176_M [mm] "176-Pin Thin Quad Flat Pack (TQ176), IPC Low Density"
height 1.6
pads (176):
  oval 2.1x0.3 smd: 1(-12.6,10.75) 2(-12.6,10.25) 3(-12.6,9.75) 4(-12.6,9.25) 5(-12.6,8.75) 6(-12.6,8.25) 7(-12.6,7.75) 8(-12.6,7.25) 9(-12.6,6.75) 10(-12.6,6.25) 11(-12.6,5.75) 12(-12.6,5.25) 13(-12.6,4.75) 14(-12.6,4.25) 15(-12.6,3.75) 16(-12.6,3.25) 17(-12.6,2.75) 18(-12.6,2.25) 19(-12.6,1.75) 20(-12.6,1.25) 21(-12.6,0.75) 22(-12.6,0.25) 23(-12.6,-0.25) 24(-12.6,-0.75) 25(-12.6,-1.25) 26(-12.6,-1.75) 27(-12.6,-2.25) 28(-12.6,-2.75) 29(-12.6,-3.25) 30(-12.6,-3.75) 31(-12.6,-4.25) 32(-12.6,-4.75) 33(-12.6,-5.25) 34(-12.6,-5.75) 35(-12.6,-6.25) 36(-12.6,-6.75) 37(-12.6,-7.25) 38(-12.6,-7.75) 39(-12.6,-8.25) 40(-12.6,-8.75) 41(-12.6,-9.25) 42(-12.6,-9.75) 43(-12.6,-10.25) 44(-12.6,-10.75) 89(12.6,-10.75) 90(12.6,-10.25) 91(12.6,-9.75) 92(12.6,-9.25) 93(12.6,-8.75) 94(12.6,-8.25) 95(12.6,-7.75) 96(12.6,-7.25) 97(12.6,-6.75) 98(12.6,-6.25) 99(12.6,-5.75) 100(12.6,-5.25) 101(12.6,-4.75) 102(12.6,-4.25) 103(12.6,-3.75) 104(12.6,-3.25) 105(12.6,-2.75) 106(12.6,-2.25) 107(12.6,-1.75) 108(12.6,-1.25) 109(12.6,-0.75) 110(12.6,-0.25) 111(12.6,0.25) 112(12.6,0.75) 113(12.6,1.25) 114(12.6,1.75) 115(12.6,2.25) 116(12.6,2.75) 117(12.6,3.25) 118(12.6,3.75) 119(12.6,4.25) 120(12.6,4.75) 121(12.6,5.25) 122(12.6,5.75) 123(12.6,6.25) 124(12.6,6.75) 125(12.6,7.25) 126(12.6,7.75) 127(12.6,8.25) 128(12.6,8.75) 129(12.6,9.25) 130(12.6,9.75) 131(12.6,10.25) 132(12.6,10.75)
  oval 0.3x2.1 smd: 45(-10.75,-12.6) 46(-10.25,-12.6) 47(-9.75,-12.6) 48(-9.25,-12.6) 49(-8.75,-12.6) 50(-8.25,-12.6) 51(-7.75,-12.6) 52(-7.25,-12.6) 53(-6.75,-12.6) 54(-6.25,-12.6) 55(-5.75,-12.6) 56(-5.25,-12.6) 57(-4.75,-12.6) 58(-4.25,-12.6) 59(-3.75,-12.6) 60(-3.25,-12.6) 61(-2.75,-12.6) 62(-2.25,-12.6) 63(-1.75,-12.6) 64(-1.25,-12.6) 65(-0.75,-12.6) 66(-0.25,-12.6) 67(0.25,-12.6) 68(0.75,-12.6) 69(1.25,-12.6) 70(1.75,-12.6) 71(2.25,-12.6) 72(2.75,-12.6) 73(3.25,-12.6) 74(3.75,-12.6) 75(4.25,-12.6) 76(4.75,-12.6) 77(5.25,-12.6) 78(5.75,-12.6) 79(6.25,-12.6) 80(6.75,-12.6) 81(7.25,-12.6) 82(7.75,-12.6) 83(8.25,-12.6) 84(8.75,-12.6) 85(9.25,-12.6) 86(9.75,-12.6) 87(10.25,-12.6) 88(10.75,-12.6) 133(10.75,12.6) 134(10.25,12.6) 135(9.75,12.6) 136(9.25,12.6) 137(8.75,12.6) 138(8.25,12.6) 139(7.75,12.6) 140(7.25,12.6) 141(6.75,12.6) 142(6.25,12.6) 143(5.75,12.6) 144(5.25,12.6) 145(4.75,12.6) 146(4.25,12.6) 147(3.75,12.6) 148(3.25,12.6) 149(2.75,12.6) 150(2.25,12.6) 151(1.75,12.6) 152(1.25,12.6) 153(0.75,12.6) 154(0.25,12.6) 155(-0.25,12.6) 156(-0.75,12.6) 157(-1.25,12.6) 158(-1.75,12.6) 159(-2.25,12.6) 160(-2.75,12.6) 161(-3.25,12.6) 162(-3.75,12.6) 163(-4.25,12.6) 164(-4.75,12.6) 165(-5.25,12.6) 166(-5.75,12.6) 167(-6.25,12.6) 168(-6.75,12.6) 169(-7.25,12.6) 170(-7.75,12.6) 171(-8.25,12.6) 172(-8.75,12.6) 173(-9.25,12.6) 174(-9.75,12.6) 175(-10.25,12.6) 176(-10.75,12.6)
Top Overlay:
  circle w0.6: c-10.15,10.15 r0.3
  circle w0.25: c-12.6,11.45 r0.125
  lines w0.2: -11.15,-11.15 11.15,-11.15 11.15,11.15 -11.15,11.15 -11.15,-11.15
Mechanical 13:
  circle w0.1: c-11.1,11.1 r0.5
  lines w0.1: -12,-12 12,-12 12,12 -12,12 -12,-12
Mechanical 15:
  lines w0.1: -0.5,0 0.5,0 ; 0,-0.5 0,0.5 ; -14.15,-14.15 14.15,-14.15 14.15,14.15 -14.15,14.15 -14.15,-14.15
3D body: height 1.6, standoff 0, extent -12,-12 12,12

## TQ176_N [mm] "176-Pin Thin Quad Flat Pack (TQ176), IPC Medium Density"
height 1.6
pads (176):
  oval 1.8x0.3 smd: 1(-12.55,10.75) 2(-12.55,10.25) 3(-12.55,9.75) 4(-12.55,9.25) 5(-12.55,8.75) 6(-12.55,8.25) 7(-12.55,7.75) 8(-12.55,7.25) 9(-12.55,6.75) 10(-12.55,6.25) 11(-12.55,5.75) 12(-12.55,5.25) 13(-12.55,4.75) 14(-12.55,4.25) 15(-12.55,3.75) 16(-12.55,3.25) 17(-12.55,2.75) 18(-12.55,2.25) 19(-12.55,1.75) 20(-12.55,1.25) 21(-12.55,0.75) 22(-12.55,0.25) 23(-12.55,-0.25) 24(-12.55,-0.75) 25(-12.55,-1.25) 26(-12.55,-1.75) 27(-12.55,-2.25) 28(-12.55,-2.75) 29(-12.55,-3.25) 30(-12.55,-3.75) 31(-12.55,-4.25) 32(-12.55,-4.75) 33(-12.55,-5.25) 34(-12.55,-5.75) 35(-12.55,-6.25) 36(-12.55,-6.75) 37(-12.55,-7.25) 38(-12.55,-7.75) 39(-12.55,-8.25) 40(-12.55,-8.75) 41(-12.55,-9.25) 42(-12.55,-9.75) 43(-12.55,-10.25) 44(-12.55,-10.75) 89(12.55,-10.75) 90(12.55,-10.25) 91(12.55,-9.75) 92(12.55,-9.25) 93(12.55,-8.75) 94(12.55,-8.25) 95(12.55,-7.75) 96(12.55,-7.25) 97(12.55,-6.75) 98(12.55,-6.25) 99(12.55,-5.75) 100(12.55,-5.25) 101(12.55,-4.75) 102(12.55,-4.25) 103(12.55,-3.75) 104(12.55,-3.25) 105(12.55,-2.75) 106(12.55,-2.25) 107(12.55,-1.75) 108(12.55,-1.25) 109(12.55,-0.75) 110(12.55,-0.25) 111(12.55,0.25) 112(12.55,0.75) 113(12.55,1.25) 114(12.55,1.75) 115(12.55,2.25) 116(12.55,2.75) 117(12.55,3.25) 118(12.55,3.75) 119(12.55,4.25) 120(12.55,4.75) 121(12.55,5.25) 122(12.55,5.75) 123(12.55,6.25) 124(12.55,6.75) 125(12.55,7.25) 126(12.55,7.75) 127(12.55,8.25) 128(12.55,8.75) 129(12.55,9.25) 130(12.55,9.75) 131(12.55,10.25) 132(12.55,10.75)
  oval 0.3x1.8 smd: 45(-10.75,-12.55) 46(-10.25,-12.55) 47(-9.75,-12.55) 48(-9.25,-12.55) 49(-8.75,-12.55) 50(-8.25,-12.55) 51(-7.75,-12.55) 52(-7.25,-12.55) 53(-6.75,-12.55) 54(-6.25,-12.55) 55(-5.75,-12.55) 56(-5.25,-12.55) 57(-4.75,-12.55) 58(-4.25,-12.55) 59(-3.75,-12.55) 60(-3.25,-12.55) 61(-2.75,-12.55) 62(-2.25,-12.55) 63(-1.75,-12.55) 64(-1.25,-12.55) 65(-0.75,-12.55) 66(-0.25,-12.55) 67(0.25,-12.55) 68(0.75,-12.55) 69(1.25,-12.55) 70(1.75,-12.55) 71(2.25,-12.55) 72(2.75,-12.55) 73(3.25,-12.55) 74(3.75,-12.55) 75(4.25,-12.55) 76(4.75,-12.55) 77(5.25,-12.55) 78(5.75,-12.55) 79(6.25,-12.55) 80(6.75,-12.55) 81(7.25,-12.55) 82(7.75,-12.55) 83(8.25,-12.55) 84(8.75,-12.55) 85(9.25,-12.55) 86(9.75,-12.55) 87(10.25,-12.55) 88(10.75,-12.55) 133(10.75,12.55) 134(10.25,12.55) 135(9.75,12.55) 136(9.25,12.55) 137(8.75,12.55) 138(8.25,12.55) 139(7.75,12.55) 140(7.25,12.55) 141(6.75,12.55) 142(6.25,12.55) 143(5.75,12.55) 144(5.25,12.55) 145(4.75,12.55) 146(4.25,12.55) 147(3.75,12.55) 148(3.25,12.55) 149(2.75,12.55) 150(2.25,12.55) 151(1.75,12.55) 152(1.25,12.55) 153(0.75,12.55) 154(0.25,12.55) 155(-0.25,12.55) 156(-0.75,12.55) 157(-1.25,12.55) 158(-1.75,12.55) 159(-2.25,12.55) 160(-2.75,12.55) 161(-3.25,12.55) 162(-3.75,12.55) 163(-4.25,12.55) 164(-4.75,12.55) 165(-5.25,12.55) 166(-5.75,12.55) 167(-6.25,12.55) 168(-6.75,12.55) 169(-7.25,12.55) 170(-7.75,12.55) 171(-8.25,12.55) 172(-8.75,12.55) 173(-9.25,12.55) 174(-9.75,12.55) 175(-10.25,12.55) 176(-10.75,12.55)
Top Overlay:
  circle w0.25: c-12.55,11.45 r0.125
  circle w0.6: c-10.25,10.25 r0.3
  lines w0.2: -11.25,-11.25 -11.25,11.25 11.25,11.25 11.25,-11.25 -11.25,-11.25
Mechanical 13:
  circle w0.1: c-11.1,11.1 r0.5
  lines w0.1: -12,-12 -12,12 12,12 12,-12 -12,-12
Mechanical 15:
  lines w0.1: -0.5,0 0.5,0 ; 0,-0.5 0,0.5 ; -13.7,-13.7 -13.7,13.7 13.7,13.7 13.7,-13.7 -13.7,-13.7
3D body: height 1.6, standoff 0, extent -12,-12 12,12

## TQG100_L [mm] "100-Pin Thin Quad Flat Pack (TQG100) - Pb-Free, IPC High Density"
height 1.6
pads (100):
  oval 1.55x0.25 smd: 1(-7.525,6) 2(-7.525,5.5) 3(-7.525,5) 4(-7.525,4.5) 5(-7.525,4) 6(-7.525,3.5) 7(-7.525,3) 8(-7.525,2.5) 9(-7.525,2) 10(-7.525,1.5) 11(-7.525,1) 12(-7.525,0.5) 13(-7.525,0) 14(-7.525,-0.5) 15(-7.525,-1) 16(-7.525,-1.5) 17(-7.525,-2) 18(-7.525,-2.5) 19(-7.525,-3) 20(-7.525,-3.5) 21(-7.525,-4) 22(-7.525,-4.5) 23(-7.525,-5) 24(-7.525,-5.5) 25(-7.525,-6) 51(7.525,-6) 52(7.525,-5.5) 53(7.525,-5) 54(7.525,-4.5) 55(7.525,-4) 56(7.525,-3.5) 57(7.525,-3) 58(7.525,-2.5) 59(7.525,-2) 60(7.525,-1.5) 61(7.525,-1) 62(7.525,-0.5) 63(7.525,0) 64(7.525,0.5) 65(7.525,1) 66(7.525,1.5) 67(7.525,2) 68(7.525,2.5) 69(7.525,3) 70(7.525,3.5) 71(7.525,4) 72(7.525,4.5) 73(7.525,5) 74(7.525,5.5) 75(7.525,6)
  oval 0.25x1.55 smd: 26(-6,-7.525) 27(-5.5,-7.525) 28(-5,-7.525) 29(-4.5,-7.525) 30(-4,-7.525) 31(-3.5,-7.525) 32(-3,-7.525) 33(-2.5,-7.525) 34(-2,-7.525) 35(-1.5,-7.525) 36(-1,-7.525) 37(-0.5,-7.525) 38(0,-7.525) 39(0.5,-7.525) 40(1,-7.525) 41(1.5,-7.525) 42(2,-7.525) 43(2.5,-7.525) 44(3,-7.525) 45(3.5,-7.525) 46(4,-7.525) 47(4.5,-7.525) 48(5,-7.525) 49(5.5,-7.525) 50(6,-7.525) 76(6,7.525) 77(5.5,7.525) 78(5,7.525) 79(4.5,7.525) 80(4,7.525) 81(3.5,7.525) 82(3,7.525) 83(2.5,7.525) 84(2,7.525) 85(1.5,7.525) 86(1,7.525) 87(0.5,7.525) 88(0,7.525) 89(-0.5,7.525) 90(-1,7.525) 91(-1.5,7.525) 92(-2,7.525) 93(-2.5,7.525) 94(-3,7.525) 95(-3.5,7.525) 96(-4,7.525) 97(-4.5,7.525) 98(-5,7.525) 99(-5.5,7.525) 100(-6,7.525)
Top Overlay:
  circle w0.25: c-7.525,6.675 r0.125
  circle w0.6: c-5.35,5.35 r0.3
  lines w0.2: -6.35,-6.35 -6.35,6.35 6.35,6.35 6.35,-6.35 -6.35,-6.35
Mechanical 13:
  circle w0.1: c-6.1,6.1 r0.5
  lines w0.1: -7,-7 -7,7 7,7 7,-7 -7,-7
Mechanical 15:
  lines w0.1: -0.5,0 0.5,0 ; 0,-0.5 0,0.5 ; -8.4,-8.4 -8.4,8.4 8.4,8.4 8.4,-8.4 -8.4,-8.4
3D body: height 1.6, standoff 0, extent -7,-7 7,7

## TQG100_M [mm] "100-Pin Thin Quad Flat Pack (TQG100) - Pb-Free, IPC Low Density"
height 1.6
pads (100):
  oval 2.1x0.3 smd: 1(-7.6,6) 2(-7.6,5.5) 3(-7.6,5) 4(-7.6,4.5) 5(-7.6,4) 6(-7.6,3.5) 7(-7.6,3) 8(-7.6,2.5) 9(-7.6,2) 10(-7.6,1.5) 11(-7.6,1) 12(-7.6,0.5) 13(-7.6,0) 14(-7.6,-0.5) 15(-7.6,-1) 16(-7.6,-1.5) 17(-7.6,-2) 18(-7.6,-2.5) 19(-7.6,-3) 20(-7.6,-3.5) 21(-7.6,-4) 22(-7.6,-4.5) 23(-7.6,-5) 24(-7.6,-5.5) 25(-7.6,-6) 51(7.6,-6) 52(7.6,-5.5) 53(7.6,-5) 54(7.6,-4.5) 55(7.6,-4) 56(7.6,-3.5) 57(7.6,-3) 58(7.6,-2.5) 59(7.6,-2) 60(7.6,-1.5) 61(7.6,-1) 62(7.6,-0.5) 63(7.6,0) 64(7.6,0.5) 65(7.6,1) 66(7.6,1.5) 67(7.6,2) 68(7.6,2.5) 69(7.6,3) 70(7.6,3.5) 71(7.6,4) 72(7.6,4.5) 73(7.6,5) 74(7.6,5.5) 75(7.6,6)
  oval 0.3x2.1 smd: 26(-6,-7.6) 27(-5.5,-7.6) 28(-5,-7.6) 29(-4.5,-7.6) 30(-4,-7.6) 31(-3.5,-7.6) 32(-3,-7.6) 33(-2.5,-7.6) 34(-2,-7.6) 35(-1.5,-7.6) 36(-1,-7.6) 37(-0.5,-7.6) 38(0,-7.6) 39(0.5,-7.6) 40(1,-7.6) 41(1.5,-7.6) 42(2,-7.6) 43(2.5,-7.6) 44(3,-7.6) 45(3.5,-7.6) 46(4,-7.6) 47(4.5,-7.6) 48(5,-7.6) 49(5.5,-7.6) 50(6,-7.6) 76(6,7.6) 77(5.5,7.6) 78(5,7.6) 79(4.5,7.6) 80(4,7.6) 81(3.5,7.6) 82(3,7.6) 83(2.5,7.6) 84(2,7.6) 85(1.5,7.6) 86(1,7.6) 87(0.5,7.6) 88(0,7.6) 89(-0.5,7.6) 90(-1,7.6) 91(-1.5,7.6) 92(-2,7.6) 93(-2.5,7.6) 94(-3,7.6) 95(-3.5,7.6) 96(-4,7.6) 97(-4.5,7.6) 98(-5,7.6) 99(-5.5,7.6) 100(-6,7.6)
Top Overlay:
  circle w0.6: c-5.15,5.15 r0.3
  circle w0.25: c-7.6,6.7 r0.125
  lines w0.2: -6.15,-6.15 6.15,-6.15 6.15,6.15 -6.15,6.15 -6.15,-6.15
Mechanical 13:
  circle w0.1: c-6.1,6.1 r0.5
  lines w0.1: -7,-7 7,-7 7,7 -7,7 -7,-7
Mechanical 15:
  lines w0.1: -0.5,0 0.5,0 ; 0,-0.5 0,0.5 ; -9.15,-9.15 9.15,-9.15 9.15,9.15 -9.15,9.15 -9.15,-9.15
3D body: height 1.6, standoff 0, extent -7,-7 7,7

## TQG100_N [mm] "100-Pin Thin Quad Flat Pack (TQG100) - Pb-Free, IPC Medium Density"
height 1.6
pads (100):
  oval 1.8x0.3 smd: 1(-7.55,6) 2(-7.55,5.5) 3(-7.55,5) 4(-7.55,4.5) 5(-7.55,4) 6(-7.55,3.5) 7(-7.55,3) 8(-7.55,2.5) 9(-7.55,2) 10(-7.55,1.5) 11(-7.55,1) 12(-7.55,0.5) 13(-7.55,0) 14(-7.55,-0.5) 15(-7.55,-1) 16(-7.55,-1.5) 17(-7.55,-2) 18(-7.55,-2.5) 19(-7.55,-3) 20(-7.55,-3.5) 21(-7.55,-4) 22(-7.55,-4.5) 23(-7.55,-5) 24(-7.55,-5.5) 25(-7.55,-6) 51(7.55,-6) 52(7.55,-5.5) 53(7.55,-5) 54(7.55,-4.5) 55(7.55,-4) 56(7.55,-3.5) 57(7.55,-3) 58(7.55,-2.5) 59(7.55,-2) 60(7.55,-1.5) 61(7.55,-1) 62(7.55,-0.5) 63(7.55,0) 64(7.55,0.5) 65(7.55,1) 66(7.55,1.5) 67(7.55,2) 68(7.55,2.5) 69(7.55,3) 70(7.55,3.5) 71(7.55,4) 72(7.55,4.5) 73(7.55,5) 74(7.55,5.5) 75(7.55,6)
  oval 0.3x1.8 smd: 26(-6,-7.55) 27(-5.5,-7.55) 28(-5,-7.55) 29(-4.5,-7.55) 30(-4,-7.55) 31(-3.5,-7.55) 32(-3,-7.55) 33(-2.5,-7.55) 34(-2,-7.55) 35(-1.5,-7.55) 36(-1,-7.55) 37(-0.5,-7.55) 38(0,-7.55) 39(0.5,-7.55) 40(1,-7.55) 41(1.5,-7.55) 42(2,-7.55) 43(2.5,-7.55) 44(3,-7.55) 45(3.5,-7.55) 46(4,-7.55) 47(4.5,-7.55) 48(5,-7.55) 49(5.5,-7.55) 50(6,-7.55) 76(6,7.55) 77(5.5,7.55) 78(5,7.55) 79(4.5,7.55) 80(4,7.55) 81(3.5,7.55) 82(3,7.55) 83(2.5,7.55) 84(2,7.55) 85(1.5,7.55) 86(1,7.55) 87(0.5,7.55) 88(0,7.55) 89(-0.5,7.55) 90(-1,7.55) 91(-1.5,7.55) 92(-2,7.55) 93(-2.5,7.55) 94(-3,7.55) 95(-3.5,7.55) 96(-4,7.55) 97(-4.5,7.55) 98(-5,7.55) 99(-5.5,7.55) 100(-6,7.55)
Top Overlay:
  circle w0.6: c-5.25,5.25 r0.3
  circle w0.25: c-7.55,6.7 r0.125
  lines w0.2: -6.25,-6.25 6.25,-6.25 6.25,6.25 -6.25,6.25 -6.25,-6.25
Mechanical 13:
  circle w0.1: c-6.1,6.1 r0.5
  lines w0.1: -7,-7 7,-7 7,7 -7,7 -7,-7
Mechanical 15:
  lines w0.1: -0.5,0 0.5,0 ; 0,-0.5 0,0.5 ; -8.7,-8.7 8.7,-8.7 8.7,8.7 -8.7,8.7 -8.7,-8.7
3D body: height 1.6, standoff 0, extent -7,-7 7,7

## TQG144_L [mm] "144-Pin Thin Quad Flat Pack (TQG144) - Pb-Free, IPC High Density"
height 1.6
pads (144):
  oval 1.55x0.25 smd: 1(-10.525,8.75) 2(-10.525,8.25) 3(-10.525,7.75) 4(-10.525,7.25) 5(-10.525,6.75) 6(-10.525,6.25) 7(-10.525,5.75) 8(-10.525,5.25) 9(-10.525,4.75) 10(-10.525,4.25) 11(-10.525,3.75) 12(-10.525,3.25) 13(-10.525,2.75) 14(-10.525,2.25) 15(-10.525,1.75) 16(-10.525,1.25) 17(-10.525,0.75) 18(-10.525,0.25) 19(-10.525,-0.25) 20(-10.525,-0.75) 21(-10.525,-1.25) 22(-10.525,-1.75) 23(-10.525,-2.25) 24(-10.525,-2.75) 25(-10.525,-3.25) 26(-10.525,-3.75) 27(-10.525,-4.25) 28(-10.525,-4.75) 29(-10.525,-5.25) 30(-10.525,-5.75) 31(-10.525,-6.25) 32(-10.525,-6.75) 33(-10.525,-7.25) 34(-10.525,-7.75) 35(-10.525,-8.25) 36(-10.525,-8.75) 73(10.525,-8.75) 74(10.525,-8.25) 75(10.525,-7.75) 76(10.525,-7.25) 77(10.525,-6.75) 78(10.525,-6.25) 79(10.525,-5.75) 80(10.525,-5.25) 81(10.525,-4.75) 82(10.525,-4.25) 83(10.525,-3.75) 84(10.525,-3.25) 85(10.525,-2.75) 86(10.525,-2.25) 87(10.525,-1.75) 88(10.525,-1.25) 89(10.525,-0.75) 90(10.525,-0.25) 91(10.525,0.25) 92(10.525,0.75) 93(10.525,1.25) 94(10.525,1.75) 95(10.525,2.25) 96(10.525,2.75) 97(10.525,3.25) 98(10.525,3.75) 99(10.525,4.25) 100(10.525,4.75) 101(10.525,5.25) 102(10.525,5.75) 103(10.525,6.25) 104(10.525,6.75) 105(10.525,7.25) 106(10.525,7.75) 107(10.525,8.25) 108(10.525,8.75)
  oval 0.25x1.55 smd: 37(-8.75,-10.525) 38(-8.25,-10.525) 39(-7.75,-10.525) 40(-7.25,-10.525) 41(-6.75,-10.525) 42(-6.25,-10.525) 43(-5.75,-10.525) 44(-5.25,-10.525) 45(-4.75,-10.525) 46(-4.25,-10.525) 47(-3.75,-10.525) 48(-3.25,-10.525) 49(-2.75,-10.525) 50(-2.25,-10.525) 51(-1.75,-10.525) 52(-1.25,-10.525) 53(-0.75,-10.525) 54(-0.25,-10.525) 55(0.25,-10.525) 56(0.75,-10.525) 57(1.25,-10.525) 58(1.75,-10.525) 59(2.25,-10.525) 60(2.75,-10.525) 61(3.25,-10.525) 62(3.75,-10.525) 63(4.25,-10.525) 64(4.75,-10.525) 65(5.25,-10.525) 66(5.75,-10.525) 67(6.25,-10.525) 68(6.75,-10.525) 69(7.25,-10.525) 70(7.75,-10.525) 71(8.25,-10.525) 72(8.75,-10.525) 109(8.75,10.525) 110(8.25,10.525) 111(7.75,10.525) 112(7.25,10.525) 113(6.75,10.525) 114(6.25,10.525) 115(5.75,10.525) 116(5.25,10.525) 117(4.75,10.525) 118(4.25,10.525) 119(3.75,10.525) 120(3.25,10.525) 121(2.75,10.525) 122(2.25,10.525) 123(1.75,10.525) 124(1.25,10.525) 125(0.75,10.525) 126(0.25,10.525) 127(-0.25,10.525) 128(-0.75,10.525) 129(-1.25,10.525) 130(-1.75,10.525) 131(-2.25,10.525) 132(-2.75,10.525) 133(-3.25,10.525) 134(-3.75,10.525) 135(-4.25,10.525) 136(-4.75,10.525) 137(-5.25,10.525) 138(-5.75,10.525) 139(-6.25,10.525) 140(-6.75,10.525) 141(-7.25,10.525) 142(-7.75,10.525) 143(-8.25,10.525) 144(-8.75,10.525)
Top Overlay:
  circle w0.6: c-8.35,8.35 r0.3
  circle w0.25: c-10.525,9.425 r0.125
  lines w0.2: -9.35,-9.35 9.35,-9.35 9.35,9.35 -9.35,9.35 -9.35,-9.35
Mechanical 13:
  circle w0.1: c-9.1,9.1 r0.5
  lines w0.1: -10,-10 10,-10 10,10 -10,10 -10,-10
Mechanical 15:
  lines w0.1: -0.5,0 0.5,0 ; 0,-0.5 0,0.5 ; -11.4,-11.4 11.4,-11.4 11.4,11.4 -11.4,11.4 -11.4,-11.4
3D body: height 1.6, standoff 0, extent -10,-10 10,10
